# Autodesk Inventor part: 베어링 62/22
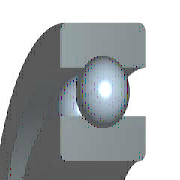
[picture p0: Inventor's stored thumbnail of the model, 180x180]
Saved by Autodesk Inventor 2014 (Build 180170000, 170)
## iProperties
Created: 2009-02
Part Number: 베어링 62/22
Material: 강, 연강
Description: 깊은 그루브 볼 베어링
Document SubType Name: Modeling
Standard: KS B 2023
Designer: KYOUNG IL JANG
Standards Organization: KS
Language: ko-KR
Size Designation: 62/22 - 22 x 50 x 14
Categories: <MemberInstance><Categories><Category DisplayName="샤프트 부품" InternalName="7f7aeb1f-a693-4053-b835-cee3144e0d98" Mnemonic="SHFT"><Category DisplayName="베어링" Inter
Density: 1 g/cm^3
Appearance: 강철
IsCustomPart: 0
Author: KYOUNG IL JANG
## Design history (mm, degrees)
sketch "스케치" dims "d0" = 7.28 (= -0.26 x WD + 0.26 x BD)
  geometry: L1 (3.36, 18)-(10.64, 18); L2 (7, 18)-(7, 14.36); L3 (7, 18)-(7, 21.64); L4 (4.295, 15.564)-(0, 15.564); L5 (0, 11)-(14, 11); L6 (4.295, 20.436)-(0, 20.436); L7 (0, 25)-(14, 25); L8 (14, 11)-(14, 15.564); L9 (9.705, 15.564)-(14, 15.564); L10 (9.705, 20.436)-(14, 20.436); L11 (14, 25)-(14, 20.436); L12 (-1.4, 0)-(8.4, 0) reference; L13 (0, -0.3)-(0, 5.3) reference
  constraints: 22 end point, 4 point on line, 2 collinear, 2 perpendicular, 2 symmetric about line, 1 midpoint, 1 parallel, 14 other
  dimensions: "d9" = 22 diameter of L5 L12 (= WD); "d11" = 50 diameter of L7 L12 (= BD); "d12" = 14 distance between parallel lines of L8 L13 (= KB); "d13" = 31.128 diameter of L9 L12 (= 0.326 x BD + 0.674 x WD)
revolve "본체" stored, may be unused: angle "d6" = 90 deg
revolve "볼" stored, may be unused: angle "d7" = 90 deg
pattern_circular "IDS_ARRAYBALL[SIMPL:T]" dims angle "d3" = 360 deg
body "Solid1"
fillet "모깎기1" dims "d1" = 1 (= KRS)
other parameters: "WD" = 22 [user parameter; used in 5 equation terms], "BD" = 50 [user parameter; used in 5 equation terms], "KB" = 14 [user parameter; used in 1 equation term], "KRS" = 1 [user parameter; used in 1 equation term], "d4" = 0, "d5" = 0, "d8" = 0, "d14" = 0, "d15" = 0, "BBA" = 0 [user parameter], "BC0" = 7154000 [user parameter], "BC" = 1.2233e+07 [user parameter], "BR" = 25 (= 0.5 x BD) [user parameter], "WR" = 11 (= 0.5 x WD) [user parameter]
